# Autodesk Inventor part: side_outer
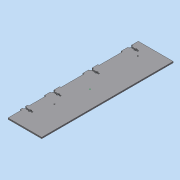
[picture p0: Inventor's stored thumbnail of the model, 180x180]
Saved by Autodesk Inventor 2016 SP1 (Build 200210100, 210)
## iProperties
Created: 2016-06
Part Number: side_outer
Material: Generic
Document SubType Name: Modeling
Designer: Mohamed A.
Density: 1 g/cm^3
Appearance: Default
d0: 1.000 ul
d0_1: 85.000 mm
d1: 320.000 mm
d2: 3.000 mm
d3: 0.00 deg
Author: Mohamed A.
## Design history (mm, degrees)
derived "side.ipt" dims count "d0" = 1
sketch "Sketch2"
  geometry: 1 further point
sketch "Sketch3"
  geometry: L1 (3, 273.4)-(0, 273.4) reference; L2 (85, 320)-(3, 320) reference; L3 (3, 273.4)-(3, 320) reference; L4 (3, 320)-(0, 320); L5 (0, 320)-(0, 278.4); L6 (0, 278.4)-(3, 278.4); L7 (3, 221.8)-(0, 221.8); L8 (0, 221.8)-(0, 185.2); L9 (0, 185.2)-(3, 185.2); L10 (0, 226.8)-(3, 226.8) reference; L11 (3, 180.2)-(0, 180.2) reference; L12 (0, 128.6)-(3, 128.6); L13 (3, 128.6)-(3, 92); L14 (3, 92)-(0, 92); L15 (0, 92)-(0, 128.6); L16 (0, 133.6)-(3, 133.6) reference; L17 (3, 221.8)-(3, 185.2); L18 (3, 226.8)-(3, 180.2) reference; L19 (3, 56)-(3, 28) reference; L20 (3, 51)-(0, 51); L21 (0, 51)-(0, 33); L22 (0, 33)-(3, 33); L23 (3, 33)-(3, 51); L24 (0, 56)-(3, 56) reference; L25 (3, 28)-(0, 28) reference; L26 (3, 87)-(0, 87) reference; 1 further point
  constraints: 30 end point, 6 perpendicular, 4 horizontal, 4 parallel, 2 collinear, 2 point on line
  dimensions: "d4" = 5 distance between parallel lines of L1 L6; "d5" = 5 distance between parallel lines of L10 L7; "d6" = 5 distance between parallel lines of L11 L9; "d7" = 5 distance between parallel lines of L16 L12; "d58" = 5 distance between parallel lines of L24 L20; "d59" = 5 distance between parallel lines of L25 L22; "d72" = 5 distance between parallel lines of L26 L14
extrude "Extrusion1" join sketch "Sketch3" distance "d9" = 3; taper "d10" = 0 deg
sketch "Sketch4"
  geometry: L1 (0, 273.4)-(3, 273.4) reference; L2 (0, 273.4)-(3, 273.4); L3 (3, 273.4)-(3, 226.8); L4 (3, 226.8)-(0, 226.8); L5 (0, 226.8)-(0, 273.4); L6 (0, 180.2)-(3, 180.2) reference; L7 (0, 180.2)-(3, 180.2); L8 (3, 180.2)-(3, 133.424); L9 (3, 133.424)-(0, 133.424); L10 (0, 133.424)-(0, 180.2); L11 (0, 248.55)-(0, 251.65); L12 (0, 28)-(0, 56) reference; L13 (0, 87)-(3, 87); L14 (3, 87)-(3, 56); L15 (3, 56)-(0, 56); L16 (0, 56)-(0, 87); L17 (0, 28)-(0, 0) reference; L18 (0, 28)-(3, 28); L19 (3, 28)-(3, 0); L20 (3, 0)-(0, 0); L21 (0, 0)-(0, 28); 1 further point
  constraints: 34 end point, 8 parallel, 4 horizontal, 4 perpendicular, 3 point on line
extrude "Extrusion2" cut sketch "Sketch4" distance "d11" = 3; taper "d12" = 0 deg
sketch "Sketch5"
  geometry: L1 (0, 300.75)-(21, 300.75); L2 (21, 300.75)-(21, 297.65); L3 (21, 297.65)-(0, 297.65); L4 (0, 297.65)-(0, 300.75); L5 (13, 302.2)-(16, 302.2); L6 (16, 302.2)-(16, 296.2); L7 (16, 296.2)-(13, 296.2); L8 (13, 296.2)-(13, 302.2); L9 (25.696, 299.2)-(-8.259, 299.2); L10 (0, 278.4)-(0, 320) reference; L11 (3, 278.4)-(0, 278.4) reference; L12 (85, 320)-(0, 320) reference; L13 (0, 303.7)-(3, 303.7); L14 (3, 303.7)-(3, 294.7); L15 (3, 294.7)-(0, 294.7); L16 (0, 294.7)-(0, 303.7); L17 (3, 221.8)-(0, 221.8) reference; L18 (21, 201.95)-(0, 201.95); L19 (0, 205.05)-(21, 205.05); L20 (21, 205.05)-(21, 201.95); L21 (16, 200.5)-(13, 200.5); L22 (13, 200.5)-(13, 206.5); L23 (0, 208)-(3, 208); L24 (3, 208)-(3, 199); L25 (16, 206.5)-(16, 200.5); L26 (13, 206.5)-(16, 206.5); L27 (3, 199)-(0, 199); L28 (25.696, 203.5)-(-8.259, 203.5); L29 (0, 199)-(0, 208); L30 (21, 108.75)-(0, 108.75); L31 (0, 111.85)-(21, 111.85); L32 (21, 111.85)-(21, 108.75); L33 (16, 107.3)-(13, 107.3); L34 (13, 107.3)-(13, 113.3); L35 (0, 114.8)-(3, 114.8); L36 (3, 114.8)-(3, 105.8); L37 (16, 113.3)-(16, 107.3); L38 (13, 113.3)-(16, 113.3); L39 (3, 105.8)-(0, 105.8); L40 (25.696, 110.3)-(-8.259, 110.3); L41 (0, 105.8)-(0, 114.8); L42 (0, 185.2)-(3, 185.2) reference; L43 (3, 92)-(0, 92) reference; L44 (0, 128.6)-(3, 128.6) reference; L45 (0, 205.05)-(0, 201.95); L46 (0, 221.8)-(0, 185.2) reference; L47 (0, 111.85)-(0, 108.75); L48 (0, 92)-(0, 128.6) reference; L49 (0, 43.55)-(21, 43.55); L50 (0, 38.25)-(0, 45.75); L51 (0, 43.55)-(0, 40.45); L52 (21, 40.45)-(0, 40.45); L53 (3, 38.25)-(0, 38.25); L54 (0, 45.75)-(3, 45.75); L55 (3, 45.75)-(3, 38.25); L56 (13, 39)-(13, 45); L57 (13, 45)-(16, 45); L58 (16, 39)-(13, 39); L59 (16, 45)-(16, 39); L60 (21, 43.55)-(21, 40.45); L61 (25.696, 42)-(-8.259, 42); L62 (0, 33)-(3, 33) reference; L63 (3, 51)-(0, 51) reference; 1 further point
  constraints: 104 end point, 21 parallel, 16 horizontal, 12 perpendicular, 3 collinear, 1 point on line, 12 other
  dimensions: "d27" = 21 distance of L2.end L3.end; "d28" = 3.1 distance of L1.end L2.end; "d29" = 3 distance of L6.end L7.end; "d30" = 6 distance of L5.end L6.end; "d31" = 41.6 distance between parallel lines of L11 L12 (derived); "d32" = 20.8 distance between parallel lines of L9 L12 (= 0.5 x d31); "d33" = 5 distance between parallel lines of L6 L2; "d34" = 9 distance between parallel lines of L15 L13; "d35" = 3 distance between parallel lines of L16 L14; "d36" = 56.6 distance between parallel lines of L17 L11 (derived); "d37" = 21 distance of L18.start L18.end; "d38" = 3.1 distance of L19.end L18.start; "d39" = 3 distance of L21.start L21.end; "d40" = 6 distance of L25.start L21.start; "d41" = 5 distance between parallel lines of L25 L20; "d42" = 9 distance between parallel lines of L27 L23; "d43" = 3 distance between parallel lines of L29 L24; "d44" = 21 distance of L30.start L30.end; "d45" = 3.1 distance of L31.end L30.start; "d46" = 3 distance of L33.start L33.end; "d47" = 6 distance of L37.start L33.start; "d48" = 5 distance between parallel lines of L37 L32; "d49" = 9 distance between parallel lines of L39 L35; "d50" = 3 distance between parallel lines of L41 L36; "d52" = 36.6 distance between parallel lines of L17 L42 (derived); "d53" = 18.3 distance between parallel lines of L28 L17 (= 0.5 x d52); "d54" = 36.6 distance between parallel lines of L43 L44 (derived); "d55" = 18.3 distance between parallel lines of L44 L40 (= 0.5 x d54); "d60" = 21 distance of L52.start L51.end; "d61" = 3.1 distance of L49.end L52.start; "d62" = 3 distance of L58.start L56.start; "d63" = 6 distance of L57.end L58.start; "d64" = 5 distance between parallel lines of L59 L60; "d65" = 7.5 distance between parallel lines of L53 L54; "d66" = 3 distance between parallel lines of L50 L55; "d67" = 18 distance between parallel lines of L62 L63 (derived); "d68" = 9 distance between parallel lines of L61 L63 (= 0.5 x d67)
extrude "Extrusion3" cut sketch "Sketch5" distance "d56" = 3; taper "d57" = 0 deg
feature "Solid1::side.ipt" dims count "d0" = 1
tag "TaggingFeature1"
body "Solid1"
other parameters: "d0_1" = 85, "d1" = 320, "d2" = 3, "d3" = 0 deg
